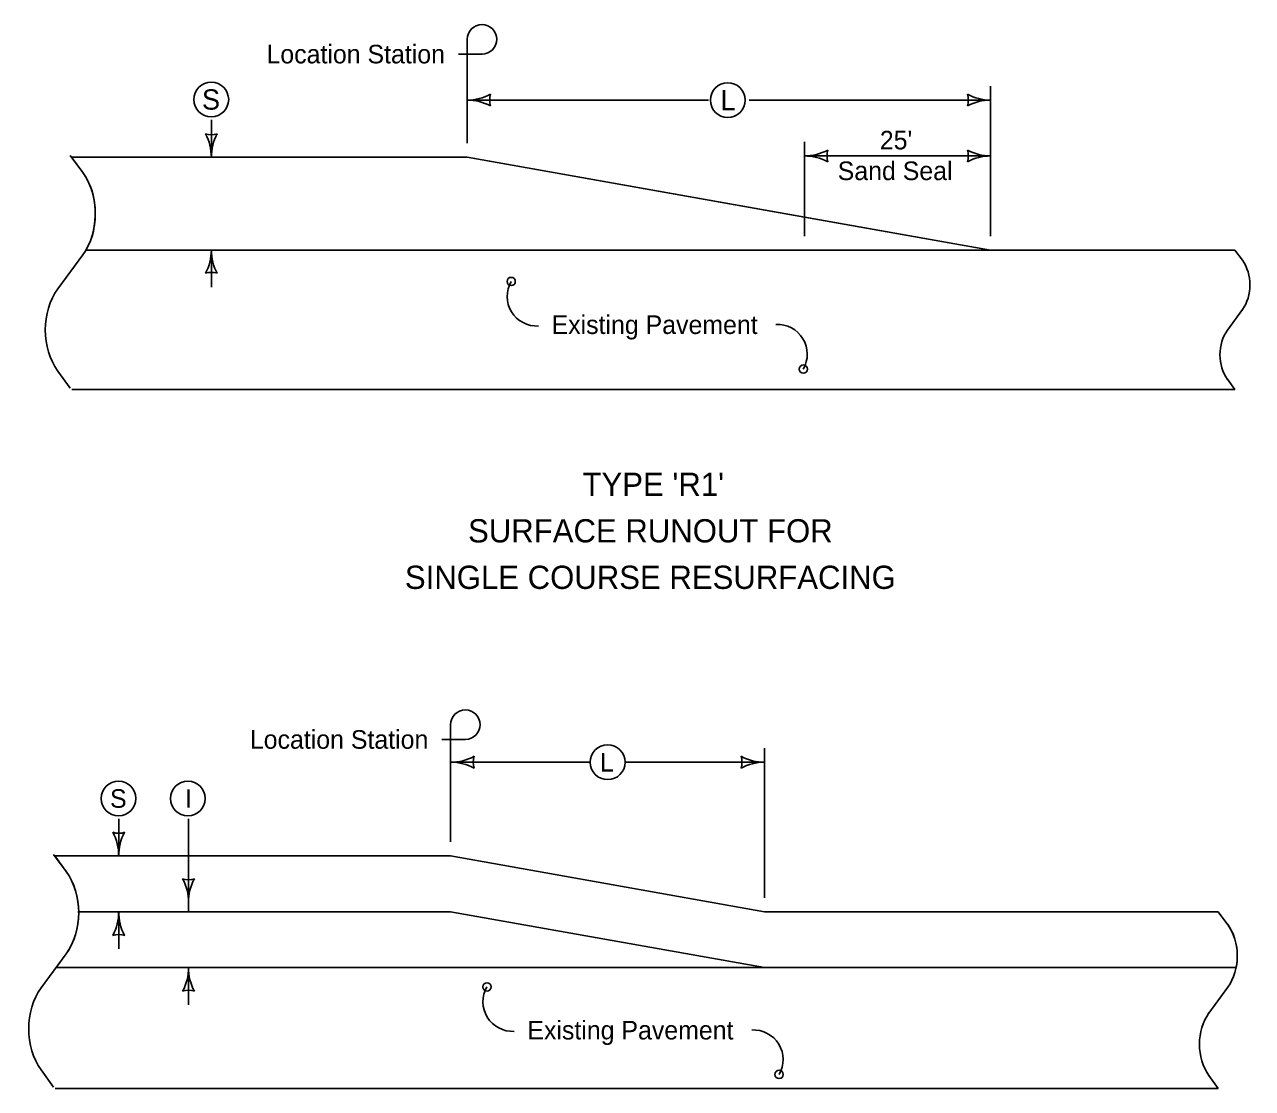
# Model space of a CAD drawing. Extents: x 10133 to 81668, y 2218 to 11018.
# Drawn here: x 19010 to 20066, y 3164 to 4079 of the extents above; entities that cross this region are included whole.
import ezdxf

# ---------------------------------------------------------------- set-up
doc = ezdxf.new("R2010")
doc.units = 0
for name, color, linetype in [('dsnNonPlotable', 7, 'Continuous'), ('dsnStdBlock', 7, 'Continuous'), ('dsnStdBlockNotModified', 7, 'Continuous'), ('dsnStgShadingPropPav', 7, 'Continuous'), ('Level 7', 7, 'Continuous')]:
    doc.layers.add(name, color=color, linetype=linetype)

msp = doc.modelspace()

# ---------------------------------------------------------------- linework, layer by layer
at = {"layer": 'dsnNonPlotable'}
for p, q in [((19376.2, 3363.6), (19035.9, 3363.6)), ((19035.9, 3363.6), (19045.7, 3350.2)), ((19376.2, 3363.6), (19035.9, 3363.6)), ((19035.9, 3363.6), (19045.7, 3350.2)), ((19646.2, 3315.6), (19376.2, 3363.6)), ((19646.2, 3315.6), (19376.2, 3363.6)), ((20036.2, 3315.6), (19646.2, 3315.6)), ((20036.2, 3315.6), (19646.2, 3315.6)), ((20044.4, 3304.4), (20036.2, 3315.6)), ((20044.4, 3304.4), (20036.2, 3315.6)), ((19045.7, 3279.5), (19037, 3267.6)), ((19045.7, 3279.5), (19037, 3267.6)), ((19037, 3267.6), (19646.2, 3267.6)), ((19037, 3267.6), (19646.2, 3267.6)), ((19646.2, 3267.6), (20051.6, 3267.6)), ((19646.2, 3267.6), (20051.6, 3267.6))]:
    msp.add_line(p, q, dxfattribs=at)
for centre, major_axis, ratio, start_param in [((19019.8, 3314.8), (0, -50), 0.732645, 0.785304), ((19019.8, 3314.8), (0, -50), 0.732645, 0.785304), ((20024.7, 3277.6), (0, -38), 0.732598, 1.304509), ((20024.7, 3277.6), (0, -38), 0.732598, 1.304509)]:
    msp.add_ellipse(centre, major_axis=major_axis, ratio=ratio, start_param=start_param, end_param=2.356194, dxfattribs=at)
at = {"layer": 'dsnStdBlock'}
for p, q in [((19390.5, 4045.8), (19390.5, 4066.1)), ((19390.5, 4045.8), (19390.5, 4066.1)), ((19403.2, 4053.4), (19382.9, 4053.4)), ((19403.2, 4053.4), (19382.9, 4053.4)), ((19390.5, 4045.8), (19390.5, 3976.8)), ((19390.5, 4045.8), (19390.5, 3976.8)), ((19840.5, 4025.8), (19840.5, 3896.8)), ((19840.5, 4025.8), (19840.5, 3896.8)), ((19390.5, 4013.8), (19598, 4013.8)), ((19390.5, 4013.8), (19598, 4013.8)), ((19633, 4013.8), (19840.5, 4013.8)), ((19633, 4013.8), (19840.5, 4013.8)), ((19170.5, 3996.8), (19170.5, 3964.8)), ((19170.5, 3996.8), (19170.5, 3964.8)), ((19680.5, 3977.8), (19680.5, 3896.8)), ((19680.5, 3977.8), (19680.5, 3896.8)), ((19049.2, 3966.1), (19060, 3951.4)), ((19049.2, 3966.1), (19060, 3951.4)), ((19050.2, 3964.8), (19390.5, 3964.8)), ((19050.2, 3964.8), (19060, 3951.4)), ((19050.2, 3964.8), (19390.5, 3964.8)), ((19050.2, 3964.8), (19060, 3951.4)), ((19840.5, 3884.8), (19390.5, 3964.8)), ((19840.5, 3884.8), (19390.5, 3964.8)), ((19680.5, 3965.8), (19840.5, 3965.8)), ((19680.5, 3965.8), (19840.5, 3965.8)), ((19062.7, 3884.8), (19840.5, 3884.8)), ((19062.7, 3884.8), (19840.5, 3884.8)), ((19170.5, 3884.8), (19170.5, 3852.8)), ((19170.5, 3884.8), (19170.5, 3852.8)), ((19840.5, 3884.8), (20050.5, 3884.8)), ((19840.5, 3884.8), (20050.5, 3884.8)), ((20050.5, 3884.8), (20057, 3876)), ((20050.5, 3884.8), (20057, 3876)), ((19060, 3880.7), (19038.5, 3851.4)), ((19060, 3880.7), (19038.5, 3851.4)), ((20057, 3833.6), (20044.1, 3816)), ((20057, 3833.6), (20044.1, 3816)), ((19038.5, 3780.7), (19049.2, 3766.1)), ((19038.5, 3780.7), (19049.2, 3766.1)), ((20044.1, 3773.6), (20050.5, 3764.8)), ((20044.1, 3773.6), (20050.5, 3764.8)), ((19050.5, 3764.8), (20050.5, 3764.8)), ((19050.5, 3764.8), (20050.5, 3764.8)), ((19376.2, 3456.2), (19376.2, 3476.5)), ((19376.2, 3456.2), (19376.2, 3476.5)), ((19388.9, 3463.8), (19368.6, 3463.8)), ((19388.9, 3463.8), (19368.6, 3463.8)), ((19376.2, 3456.2), (19376.2, 3375.6)), ((19376.2, 3456.2), (19376.2, 3375.6)), ((19646.2, 3456.2), (19646.2, 3327.6)), ((19646.2, 3456.2), (19646.2, 3327.6)), ((19376.2, 3444.2), (19496.2, 3444.2)), ((19376.2, 3444.2), (19496.2, 3444.2)), ((19526.2, 3444.2), (19646.2, 3444.2)), ((19526.2, 3444.2), (19646.2, 3444.2)), ((19090.9, 3395.6), (19090.9, 3363.6)), ((19090.9, 3395.6), (19090.9, 3363.6)), ((19150.9, 3395.6), (19150.9, 3315.6)), ((19150.9, 3395.6), (19150.9, 3315.6)), ((19034.9, 3364.8), (19045.7, 3350.2)), ((19034.9, 3364.8), (19045.7, 3350.2)), ((19036.2, 3363.6), (19376.2, 3363.6)), ((19036.2, 3363.6), (19376.2, 3363.6)), ((19646.2, 3315.6), (19376.2, 3363.6)), ((19646.2, 3315.6), (19376.2, 3363.6)), ((19055.8, 3315.6), (19376.2, 3315.6)), ((19055.8, 3315.6), (19376.2, 3315.6)), ((19090.9, 3315.6), (19090.9, 3283.6)), ((19090.9, 3315.6), (19090.9, 3283.6)), ((19646.2, 3267.6), (19376.2, 3315.6)), ((19646.2, 3267.6), (19376.2, 3315.6)), ((19646.2, 3315.6), (20036.2, 3315.6)), ((19646.2, 3315.6), (20036.2, 3315.6)), ((20036.2, 3315.6), (20044.4, 3304.4)), ((20036.2, 3315.6), (20044.4, 3304.4)), ((19045.7, 3279.5), (19024.2, 3250.2)), ((19045.7, 3279.5), (19024.2, 3250.2)), ((19037, 3267.6), (19646.2, 3267.6)), ((19037, 3267.6), (19646.2, 3267.6)), ((19150.9, 3267.6), (19150.9, 3235.6)), ((19150.9, 3267.6), (19150.9, 3235.6)), ((19646.2, 3267.6), (20051.6, 3267.6)), ((19646.2, 3267.6), (20051.6, 3267.6)), ((19826.2, 3267.6), (20036.2, 3267.6)), ((19826.2, 3267.6), (20036.2, 3267.6)), ((20044.4, 3250.7), (20028.1, 3228.4)), ((20044.4, 3250.7), (20028.1, 3228.4)), ((19024.2, 3179.5), (19034.9, 3164.8)), ((19024.2, 3179.5), (19034.9, 3164.8)), ((20028.1, 3174.7), (20036.2, 3163.6)), ((20028.1, 3174.7), (20036.2, 3163.6)), ((19036.2, 3163.6), (20036.2, 3163.6)), ((19036.2, 3163.6), (20036.2, 3163.6))]:
    msp.add_line(p, q, dxfattribs=at)
for points in [[(19390.5, 3964.8), (19170.5, 3964.8), (19050.2, 3964.8)], [(19390.5, 3964.8), (19170.5, 3964.8), (19050.2, 3964.8)], [(19840.5, 3884.8), (19680.5, 3913.2), (19390.5, 3964.8)], [(19840.5, 3884.8), (19680.5, 3913.2), (19390.5, 3964.8)], [(19062.7, 3884.8), (19170.5, 3884.8), (19840.5, 3884.8)], [(19062.7, 3884.8), (19170.5, 3884.8), (19840.5, 3884.8)]]:
    msp.add_lwpolyline(points, dxfattribs=at)
for centre, radius in [((19170.4, 4014.3), 15), ((19170.4, 4014.3), 15), ((19614.5, 4013.8), 15), ((19614.5, 4013.8), 15), ((19511.2, 3444.2), 15), ((19511.2, 3444.2), 15), ((19090.7, 3413), 15), ((19090.7, 3413), 15), ((19150.3, 3413), 15), ((19150.3, 3413), 15), ((19407.5, 3250.9), 3.56), ((19407.5, 3250.9), 3.56), ((19658.6, 3175.6), 3.56), ((19658.6, 3175.6), 3.56)]:
    msp.add_circle(centre, radius, dxfattribs=at)
for centre, radius, start, end in [((19403.2, 4066.1), 12.7, 270, 180), ((19403.2, 4066.1), 12.7, 270, 180), ((19450.4, 3845), 25.6, 150.0683, 272.8436), ((19450.4, 3845), 25.6, 150.0683, 272.8436), ((19657.2, 3795.2), 25.6, 330.0683, 92.8436), ((19657.2, 3795.2), 25.6, 330.0683, 92.8436), ((19388.9, 3476.5), 12.7, 270, 180), ((19388.9, 3476.5), 12.7, 270, 180), ((19376.2, 3487.4), 43.2, 270, 298.0725), ((19376.2, 3487.4), 43.2, 270, 298.0725), ((19376.2, 3401), 43.2, 61.9275, 90), ((19376.2, 3401), 43.2, 61.9275, 90), ((19412.4, 3444.2), 16.7, 162.2666, 197.7334), ((19412.4, 3444.2), 16.7, 162.2666, 197.7334), ((19610, 3444.2), 16.7, 342.2666, 17.7333), ((19646.2, 3487.4), 43.2, 241.9275, 270), ((19610, 3444.2), 16.7, 342.2666, 17.7333), ((19646.2, 3487.4), 43.2, 241.9275, 270), ((19646.2, 3401), 43.2, 90, 118.0725), ((19646.2, 3401), 43.2, 90, 118.0725), ((19090.9, 3399.8), 16.7, 252.2666, 287.7333), ((19047.7, 3363.6), 43.2, 360, 28.0725), ((19090.9, 3399.8), 16.7, 252.2666, 287.7333), ((19047.7, 3363.6), 43.2, 360, 28.0725), ((19134, 3363.6), 43.2, 151.9275, 180), ((19134, 3363.6), 43.2, 151.9275, 180), ((19150.9, 3359.8), 16.7, 252.2666, 287.7333), ((19107.7, 3323.6), 43.2, 360, 28.0725), ((19150.9, 3359.8), 16.7, 252.2666, 287.7333), ((19107.7, 3323.6), 43.2, 360, 28.0725), ((19194, 3323.6), 43.2, 151.9275, 180), ((19194, 3323.6), 43.2, 151.9275, 180), ((19047.7, 3315.6), 43.2, 331.9275, 360), ((19047.7, 3315.6), 43.2, 331.9275, 360), ((19134, 3315.6), 43.2, 180, 208.0725), ((19134, 3315.6), 43.2, 180, 208.0725), ((19090.9, 3279.3), 16.7, 72.2666, 107.7334), ((19090.9, 3279.3), 16.7, 72.2666, 107.7334), ((19107.7, 3267.6), 43.2, 331.9275, 360), ((19107.7, 3267.6), 43.2, 331.9275, 360), ((19194, 3267.6), 43.2, 180, 208.0725), ((19194, 3267.6), 43.2, 180, 208.0725), ((19150.9, 3231.3), 16.7, 72.2666, 107.7334), ((19150.9, 3231.3), 16.7, 72.2666, 107.7334), ((19429.6, 3238.2), 25.6, 150.0683, 272.8436), ((19429.6, 3238.2), 25.6, 150.0683, 272.8436), ((19636.5, 3188.3), 25.6, 330.0683, 92.8436), ((19636.5, 3188.3), 25.6, 330.0683, 92.8436)]:
    msp.add_arc(centre, radius, start, end, dxfattribs=at)
for centre, major_axis, ratio, start_param in [((19034.1, 3916.1), (0, -50), 0.732645, 0.785398), ((19034.1, 3916.1), (0, -50), 0.732645, 0.895397), ((19034.1, 3916.1), (0, -50), 0.732645, 0.785398), ((19034.1, 3916.1), (0, -50), 0.732645, 0.895397), ((20041.4, 3854.8), (0, -30), 0.732616, 0.785398), ((20041.4, 3854.8), (0, -30), 0.732616, 0.785398), ((19064.4, 3816.1), (0, 50), 0.732645, 0.785398), ((19064.4, 3816.1), (0, 50), 0.732645, 0.785398), ((20059.6, 3794.8), (0, 30), 0.732616, 0.785398), ((20059.6, 3794.8), (0, 30), 0.732616, 0.785398), ((19019.8, 3314.8), (0, -50), 0.732645, 0.785398), ((19019.8, 3314.8), (0, -50), 0.732645, 0.785398), ((20024.7, 3277.6), (0, -38), 0.732598, 0.785398), ((20024.7, 3277.6), (0, -38), 0.732598, 0.785398), ((19050.1, 3214.8), (0, 50), 0.732645, 0.785398), ((19050.1, 3214.8), (0, 50), 0.732645, 0.785398), ((20047.8, 3201.6), (0, 38), 0.732598, 0.785398), ((20047.8, 3201.6), (0, 38), 0.732598, 0.785398)]:
    msp.add_ellipse(centre, major_axis=major_axis, ratio=ratio, start_param=start_param, end_param=2.356194, dxfattribs=at)
at = {"layer": 'dsnStgShadingPropPav'}
for centre, radius, start, end in [((19390.5, 4056.3), 42.5, 270, 298.0725), ((19390.5, 4056.3), 42.5, 270, 298.0725), ((19390.5, 3971.3), 42.5, 61.9275, 90), ((19390.5, 3971.3), 42.5, 61.9275, 90), ((19426.2, 4013.8), 16.4, 162.2666, 197.7334), ((19426.2, 4013.8), 16.4, 162.2666, 197.7334), ((19804.9, 4013.8), 16.4, 342.2666, 17.7334), ((19840.5, 4056.3), 42.5, 241.9275, 270), ((19804.9, 4013.8), 16.4, 342.2666, 17.7334), ((19840.5, 4056.3), 42.5, 241.9275, 270), ((19840.5, 3971.3), 42.5, 90, 118.0725), ((19840.5, 3971.3), 42.5, 90, 118.0725), ((19170.5, 4000.4), 16.4, 252.2666, 287.7333), ((19128, 3964.8), 42.5, 360, 28.0725), ((19170.5, 4000.4), 16.4, 252.2666, 287.7333), ((19128, 3964.8), 42.5, 360, 28.0725), ((19213, 3964.8), 42.5, 151.9275, 180), ((19213, 3964.8), 42.5, 151.9275, 180), ((19680.5, 4008.3), 42.5, 270, 298.0725), ((19680.5, 4008.3), 42.5, 270, 298.0725), ((19716.2, 3965.8), 16.4, 162.2666, 197.7334), ((19716.2, 3965.8), 16.4, 162.2666, 197.7334), ((19804.9, 3965.8), 16.4, 342.2666, 17.7334), ((19840.5, 4008.3), 42.5, 241.9275, 270), ((19804.9, 3965.8), 16.4, 342.2666, 17.7334), ((19840.5, 4008.3), 42.5, 241.9275, 270), ((19680.5, 3923.3), 42.5, 61.9275, 90), ((19680.5, 3923.3), 42.5, 61.9275, 90), ((19840.5, 3923.3), 42.5, 90, 118.0725), ((19840.5, 3923.3), 42.5, 90, 118.0725), ((19128, 3884.8), 42.5, 331.9275, 360), ((19128, 3884.8), 42.5, 331.9275, 360), ((19213, 3884.8), 42.5, 180, 208.0725), ((19213, 3884.8), 42.5, 180, 208.0725), ((19170.5, 3849.2), 16.4, 72.2666, 107.7334), ((19170.5, 3849.2), 16.4, 72.2666, 107.7334)]:
    msp.add_arc(centre, radius, start, end, dxfattribs=at)
at = {"layer": 'Level 7'}
for centre in [(19428.3, 3857.8), (19428.3, 3857.8), (19679.4, 3782.4), (19679.4, 3782.4)]:
    msp.add_circle(centre, 3.54, dxfattribs=at)

# ---------------------------------------------------------------- texts
at = {"layer": 'dsnStdBlock'}
for s, p in [('S', (19162.4, 4005.6)), ('S', (19162.4, 4005.6)), ('L', (19608.3, 4005.1)), ('L', (19608.3, 4005.1))]:
    msp.add_text(s, height=17.5, dxfattribs=at).set_placement(p)
at = {"layer": 'dsnStdBlockNotModified'}
for s, height, p in [('Location Station', 16, (19217.9, 4045.4)), ('Location Station', 16, (19217.9, 4045.4)), ("25'", 16, (19745.2, 3971.4)), ("25'", 16, (19745.2, 3971.4)), ('Sand Seal', 16, (19709, 3945)), ('Sand Seal', 16, (19709, 3945)), ('Existing Pavement', 16, (19463, 3812.6)), ('Existing Pavement', 16, (19463, 3812.6)), ("TYPE 'R1'", 20, (19489.6, 3673.3)), ("TYPE 'R1'", 20, (19489.6, 3673.3)), ('SURFACE RUNOUT FOR', 20, (19391.2, 3633.3)), ('SURFACE RUNOUT FOR', 20, (19391.2, 3633.3)), ('SINGLE COURSE RESURFACING', 20, (19336.9, 3593.3)), ('SINGLE COURSE RESURFACING', 20, (19336.9, 3593.3)), ('Location Station', 16, (19203.6, 3455.8)), ('Location Station', 16, (19203.6, 3455.8)), ('L', 16, (19504.6, 3436.2)), ('L', 16, (19504.6, 3436.2)), ('S', 16, (19083.4, 3405)), ('S', 16, (19083.4, 3405)), ('I', 16, (19147.8, 3405)), ('I', 16, (19147.8, 3405)), ('Existing Pavement', 16, (19442.2, 3205.7)), ('Existing Pavement', 16, (19442.2, 3205.7))]:
    msp.add_text(s, height=height, dxfattribs=at).set_placement(p)

doc.saveas('drawing.dxf')
